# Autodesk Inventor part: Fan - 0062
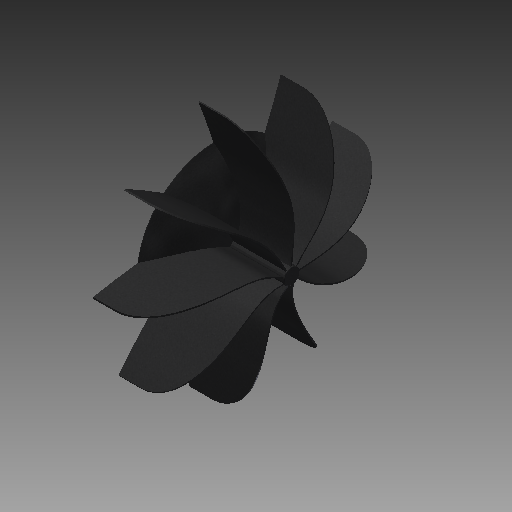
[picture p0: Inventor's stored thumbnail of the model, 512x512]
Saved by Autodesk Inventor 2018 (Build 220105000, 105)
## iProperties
Created: 2006-05
Part Number: Fan - 0062
Document SubType Name: Modeling
Designer: Autodesk, Inc.
Density: 1 g/cm^3
Description: Propeller Fan -  0062
Mass: 1278.83 g
Surface Area: 8884.25 cm^2
Volume: 1278.83 cm^3
Material: Generic
Appearance: Black Cast
Author: Autodesk, Inc.
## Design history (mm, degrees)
sketch "Sketch1"
  geometry: L1 (-343.436, 0)-(311.024, 0) reference; L2 (170, 18)-(0, 18); L3 (0, 18)-(0, 275); L4 (0, 275)-(50, 275); L5 (50, 275)-(170, 18); L6 (170, 18)-(174.823, 0); L7 (0, 18)-(170, 18); L8 (170, 18)-(170, 15); L9 (170, 15)-(0, 15); L10 (0, 15)-(0, 18); A1 r 300 centre (-249.942, 12.081) between (50, 18) and (0, 178); 2 further points
  constraints: 18 end point, 4 parallel, 4 point on line, 2 horizontal, 2 perpendicular, 2 point on circle, 1 centre point, 4 other
  dimensions: "d0" = 75 deg angle of L1 L6; "d2" = 550 diameter of L4 L1; "d3" = 50 distance of L2.end A1.start; "d4" = 50 distance of L3.end L4.end; "d5" = 160 distance from line of L3 point (160, 156.705); "d6" = 170 distance of L2.start L2.end; "d7" = 160 distance from line of L2 A1.end; "d8" = 300 radius of A1; "d9" = 3 distance between parallel lines of L2 L9; "d10" = 30 diameter of L9 L1
sketch "Sketch2"
  geometry: L1 (18, 0)-(275, 0) reference; L2 (15, 0)-(18, 0) reference; L3 (15.513, 1.41)-(14.487, -1.41); L4 (275.969, 36.421)-(274.943, 39.24); L5 (275.969, 36.421)-(516.026, 123.795); L6 (516.026, 123.795)-(515, 126.614); L7 (515, 126.614)-(274.943, 39.24); L8 (15.513, 1.41)-(12.694, 2.436); L9 (12.694, 2.436)-(11.668, -0.383); L10 (11.668, -0.383)-(14.487, -1.41); L11 (515, 126.614)-(15, 126.614); L12 (15, 126.614)-(15, 0)
  constraints: 20 end point, 5 perpendicular, 3 equal length, 2 parallel, 1 midpoint, 1 vertical, 8 other
  dimensions: "d15" = 3 distance of L4.start L4.end; "d16" = 500 distance of L6.end L11.end; "d17" = 20 deg angle of L11 L7; "d18" = 20 deg angle of L11 L8
extrude "Extrusion1" new body sketch "Sketch1" stored distance "d19" = 100; taper "d20" = 0 deg
extrude "Extrusion2" sketch "Sketch2" distance "d21" = 300; taper "d22" = 0 deg
pattern_circular "Circular Pattern1" dims "d24" = 360 deg
feature "RevolutionSrf1" dims angle "d11" = 90 deg
thicken "Thicken1" dims "d12" = 3, "d13" = 3
revolve "Revolution1" stored, may be unused: angle "d14" = 90 deg
thicken "Thicken2" dims "d26" = 3, "d27" = 3
sketch "Sketch3"
  geometry: A1 r 18 centre (0, 0) between (0, 18) and (-11.57, 13.789) reference; A2 r 18 centre (0, 0) between (-11.57, 13.789) and (-17.727, 3.126) reference; A3 r 18 centre (0, 0) between (-17.727, 3.126) and (-15.588, -9) reference; A4 r 18 centre (0, 0) between (-15.588, -9) and (-6.156, -16.914) reference; A5 r 18 centre (0, 0) between (-6.156, -16.914) and (6.156, -16.914) reference; A6 r 18 centre (0, 0) between (6.156, -16.914) and (15.588, -9) reference; A7 r 18 centre (0, 0) between (15.588, -9) and (17.727, 3.126) reference; A8 r 18 centre (0, 0) between (17.727, 3.126) and (11.57, 13.789) reference; A9 r 18 centre (0, 0) between (11.57, 13.789) and (0, 18) reference
extrude "Extrusion3" join sketch "Sketch3" distance "d28" = 2; taper "d29" = 0 deg
fillet "Fillet1" dims "d30" = 2
body "Solid1"
body "Srf1"
